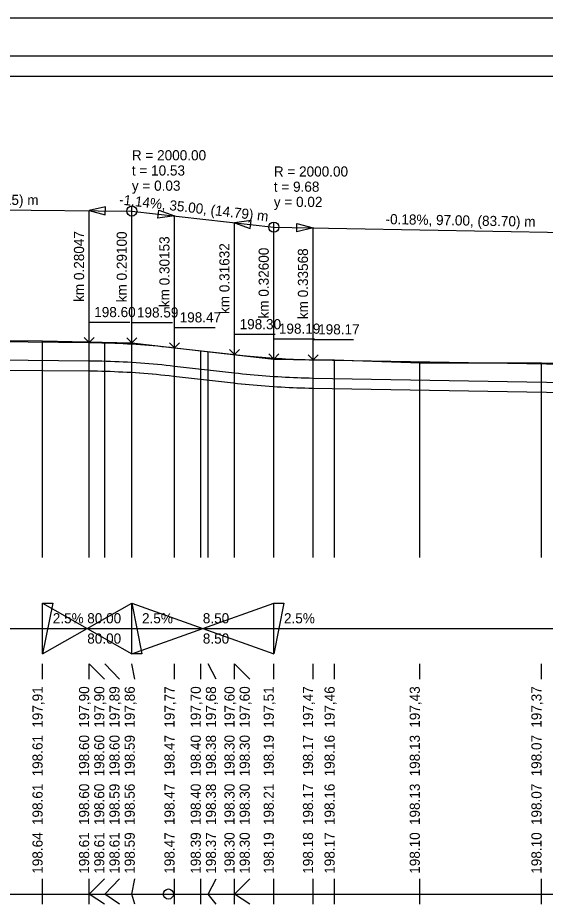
# Model space of a CAD drawing. Extents: x -51 to 53, y -74 to 15.
# Drawn here: x -12.15 to 0.85, y -6.73 to 15.15 of the extents above; entities that cross this region are included whole.
import ezdxf

# ---------------------------------------------------------------- set-up
doc = ezdxf.new("R2010")
doc.units = 0
for name, color, linetype in [('Implicitní', 7, 'Continuous'), ('KONSTRUKCE_L', 7, 'Continuous'), ('KOTY_L', 7, 'Continuous'), ('KOTY_N', 7, 'Continuous'), ('KOTY_S', 7, 'Continuous'), ('KOTY_T', 7, 'Continuous'), ('KOTY_VP', 7, 'Continuous'), ('Nová vrstva (0)', 7, 'Continuous'), ('PR_SKLON_L', 7, 'Continuous'), ('PR_SKLON_T', 7, 'Continuous'), ('ROVINA_L', 7, 'Continuous'), ('ROVINA_O', 7, 'Continuous'), ('SKLON_POMERY', 7, 'Continuous'), ('TABULKY_L', 7, 'Continuous'), ('TEREN_L', 7, 'Continuous'), ('V_POLYGON', 7, 'Continuous'), ('V_POLYGON_ZO', 7, 'Continuous')]:
    doc.layers.add(name, color=color, linetype=linetype)

msp = doc.modelspace()

# ---------------------------------------------------------------- linework, layer by layer
at = {"layer": 'Implicitní'}
msp.add_lwpolyline([(-51.392, 15.154), (53.079, 15.154), (53.079, -14.546), (-51.392, -14.546)], close=True, dxfattribs=at)
at = {"layer": 'KONSTRUKCE_L'}
for p, q in [((-16.608, 6.754), (-10.393, 6.698)), ((-10.393, 6.698), (-10.288, 6.697)), ((-10.288, 6.697), (-10.182, 6.695)), ((-10.182, 6.695), (-10.077, 6.693)), ((-10.077, 6.693), (-9.972, 6.69)), ((-9.972, 6.69), (-9.867, 6.687)), ((-9.867, 6.687), (-9.761, 6.683)), ((-9.761, 6.683), (-9.656, 6.678)), ((-9.656, 6.678), (-9.551, 6.673)), ((-9.551, 6.673), (-9.445, 6.667)), ((-9.445, 6.667), (-9.34, 6.661)), ((-9.34, 6.661), (-9.235, 6.654)), ((-9.235, 6.654), (-9.129, 6.647)), ((-9.129, 6.647), (-9.024, 6.639)), ((-9.024, 6.639), (-8.919, 6.631)), ((-8.919, 6.631), (-8.813, 6.622)), ((-8.813, 6.622), (-8.708, 6.612)), ((-8.708, 6.612), (-8.603, 6.602)), ((-8.603, 6.602), (-8.498, 6.591)), ((-8.498, 6.591), (-8.392, 6.58)), ((-8.392, 6.58), (-8.287, 6.568)), ((-8.287, 6.568), (-6.808, 6.399)), ((-6.808, 6.399), (-6.711, 6.389)), ((-6.711, 6.389), (-6.614, 6.378)), ((-6.614, 6.378), (-6.517, 6.368)), ((-6.517, 6.368), (-6.421, 6.359)), ((-6.421, 6.359), (-6.324, 6.35)), ((-6.324, 6.35), (-6.227, 6.341)), ((-6.227, 6.341), (-6.13, 6.333)), ((-6.13, 6.333), (-6.034, 6.326)), ((-6.034, 6.326), (-5.937, 6.319)), ((-5.937, 6.319), (-5.84, 6.312)), ((-5.84, 6.312), (-5.743, 6.306)), ((-5.743, 6.306), (-5.646, 6.3)), ((-5.646, 6.3), (-5.55, 6.295)), ((-5.55, 6.295), (-5.453, 6.29)), ((-5.453, 6.29), (-5.356, 6.286)), ((-5.356, 6.286), (-5.259, 6.282)), ((-5.259, 6.282), (-5.163, 6.279)), ((-5.163, 6.279), (-5.066, 6.276)), ((-5.066, 6.276), (-4.969, 6.274)), ((-4.969, 6.274), (-4.872, 6.272)), ((-4.872, 6.272), (3.497, 6.125))]:
    msp.add_line(p, q, dxfattribs=at)
at = {"layer": 'KOTY_L'}
for p, q in [((-11.54, 1.849), (-11.54, 7.189)), ((-10.393, 1.849), (-10.393, 7.163)), ((-10.393, 1.849), (-10.393, 7.163)), ((-10.01, 1.849), (-10.01, 7.154)), ((-9.34, 1.849), (-9.34, 7.139)), ((-8.287, 1.849), (-8.287, 7.015)), ((-7.64, 1.849), (-7.64, 6.939)), ((-7.462, 1.849), (-7.462, 6.919)), ((-6.808, 1.849), (-6.808, 6.846)), ((-6.808, 1.849), (-6.808, 6.846)), ((-5.84, 1.849), (-5.84, 6.739)), ((-4.872, 1.849), (-4.872, 6.726)), ((-4.34, 1.849), (-4.34, 6.719)), ((-2.24, 1.849), (-2.24, 6.649)), ((0.76, 1.849), (0.76, 6.649)), ((-11.54, -1.151), (-11.54, -0.776)), ((-10.393, -1.151), (-10.393, -0.776)), ((-10.018, -1.151), (-10.393, -0.776)), ((-9.643, -1.151), (-10.01, -0.776)), ((-9.268, -1.151), (-9.34, -0.776)), ((-8.287, -1.151), (-8.287, -0.776)), ((-7.64, -1.151), (-7.64, -0.776)), ((-7.265, -1.151), (-7.462, -0.776)), ((-6.808, -1.151), (-6.808, -0.776)), ((-6.433, -1.151), (-6.808, -0.776)), ((-5.84, -1.151), (-5.84, -0.776)), ((-4.872, -1.151), (-4.872, -0.776)), ((-4.34, -1.151), (-4.34, -0.776)), ((-2.24, -1.151), (-2.24, -0.776)), ((0.76, -1.151), (0.76, -0.776)), ((-11.54, -4.751), (-11.54, -4.751)), ((-10.393, -4.751), (-10.393, -4.751)), ((-10.018, -4.751), (-10.018, -4.751)), ((-9.643, -4.751), (-9.643, -4.751)), ((-9.268, -4.751), (-9.268, -4.751)), ((-8.287, -4.751), (-8.287, -4.751)), ((-7.64, -4.751), (-7.64, -4.751)), ((-7.265, -4.751), (-7.265, -4.751)), ((-6.808, -4.751), (-6.808, -4.751)), ((-6.433, -4.751), (-6.433, -4.751)), ((-5.84, -4.751), (-5.84, -4.751)), ((-4.872, -4.751), (-4.872, -4.751)), ((-4.34, -4.751), (-4.34, -4.751)), ((-2.24, -4.751), (-2.24, -4.751)), ((0.76, -4.751), (0.76, -4.751)), ((-11.54, -6.451), (-11.54, -6.076)), ((-10.393, -6.451), (-10.393, -6.076)), ((-10.393, -6.451), (-10.018, -6.076)), ((-10.01, -6.451), (-9.643, -6.076)), ((-9.34, -6.451), (-9.268, -6.076)), ((-8.287, -6.451), (-8.287, -6.076)), ((-7.64, -6.451), (-7.64, -6.076)), ((-7.462, -6.451), (-7.265, -6.076)), ((-6.808, -6.451), (-6.808, -6.076)), ((-6.808, -6.451), (-6.433, -6.076)), ((-5.84, -6.451), (-5.84, -6.076)), ((-4.872, -6.451), (-4.872, -6.076)), ((-4.34, -6.451), (-4.34, -6.076)), ((-2.24, -6.451), (-2.24, -6.076)), ((0.76, -6.451), (0.76, -6.076))]:
    msp.add_line(p, q, dxfattribs=at)
at = {"layer": 'KOTY_S'}
for p, q in [((-11.54, -6.701), (-11.54, -6.451)), ((-10.393, -6.701), (-10.393, -6.451)), ((-10.018, -6.701), (-10.393, -6.451)), ((-9.643, -6.701), (-10.01, -6.451)), ((-9.268, -6.701), (-9.34, -6.451)), ((-8.287, -6.701), (-8.287, -6.451)), ((-7.64, -6.701), (-7.64, -6.451)), ((-7.265, -6.701), (-7.462, -6.451)), ((-6.808, -6.701), (-6.808, -6.451)), ((-6.433, -6.701), (-6.808, -6.451)), ((-5.84, -6.701), (-5.84, -6.451)), ((-4.872, -6.701), (-4.872, -6.451)), ((-4.34, -6.701), (-4.34, -6.451)), ((-2.24, -6.701), (-2.24, -6.451)), ((0.76, -6.701), (0.76, -6.451))]:
    msp.add_line(p, q, dxfattribs=at)
at = {"layer": 'Nová vrstva (0)'}
for p, q in [((-16.61, 6.504), (-10.395, 6.448)), ((-10.396, 6.448), (-10.291, 6.447)), ((-10.292, 6.447), (-10.187, 6.445)), ((-10.188, 6.445), (-10.083, 6.443)), ((-10.084, 6.443), (-9.979, 6.44)), ((-9.98, 6.44), (-9.875, 6.437)), ((-9.876, 6.437), (-9.771, 6.433)), ((-9.772, 6.433), (-9.667, 6.428)), ((-9.668, 6.428), (-9.563, 6.423)), ((-9.564, 6.423), (-9.459, 6.418)), ((-9.46, 6.418), (-9.355, 6.412)), ((-9.356, 6.412), (-9.251, 6.405)), ((-9.252, 6.405), (-9.147, 6.398)), ((-9.148, 6.398), (-9.043, 6.39)), ((-9.044, 6.39), (-8.939, 6.381)), ((-8.94, 6.382), (-8.835, 6.373)), ((-8.836, 6.373), (-8.731, 6.363)), ((-8.732, 6.363), (-8.627, 6.353)), ((-8.628, 6.353), (-8.523, 6.343)), ((-8.524, 6.343), (-8.419, 6.332)), ((-8.42, 6.332), (-8.315, 6.32)), ((-8.315, 6.32), (-6.836, 6.151)), ((-6.835, 6.151), (-6.739, 6.14)), ((-6.737, 6.14), (-6.641, 6.13)), ((-6.639, 6.13), (-6.543, 6.12)), ((-6.542, 6.12), (-6.445, 6.11)), ((-6.444, 6.11), (-6.347, 6.101)), ((-6.346, 6.101), (-6.249, 6.092)), ((-6.248, 6.092), (-6.151, 6.084)), ((-6.15, 6.084), (-6.053, 6.077)), ((-6.052, 6.077), (-5.955, 6.069)), ((-5.954, 6.069), (-5.857, 6.063)), ((-5.856, 6.063), (-5.759, 6.057)), ((-5.758, 6.057), (-5.661, 6.051)), ((-5.66, 6.051), (-5.563, 6.046)), ((-5.562, 6.045), (-5.465, 6.041)), ((-5.464, 6.041), (-5.367, 6.036)), ((-5.366, 6.036), (-5.269, 6.033)), ((-5.268, 6.033), (-5.171, 6.029)), ((-5.17, 6.029), (-5.073, 6.026)), ((-5.072, 6.026), (-4.975, 6.024)), ((-4.974, 6.024), (-4.877, 6.022)), ((-4.877, 6.022), (3.493, 5.875))]:
    msp.add_line(p, q, dxfattribs=at)
at = {"layer": 'PR_SKLON_L'}
for p, q in [((-11.54, -0.526), (-9.34, 0.724)), ((-11.54, 0.724), (-9.34, -0.526)), ((-9.34, -0.526), (-5.84, 0.724)), ((-9.34, 0.724), (-5.84, -0.526)), ((-38.44, 0.099), (-11.54, 0.099)), ((-11.54, 0.099), (-9.34, 0.099)), ((-9.34, 0.099), (-5.84, 0.099)), ((-5.84, 0.099), (3.86, 0.099)), ((-9.34, -0.526), (-9.34, -0.526)), ((-5.84, -0.526), (-5.84, -0.526))]:
    msp.add_line(p, q, dxfattribs=at)
for points in [[(-11.54, 0.099), (-11.54, 0.724), (-11.29, 0.724), (-11.54, -0.526)], [(-9.34, 0.099), (-9.34, 0.724), (-9.09, -0.526), (-9.34, -0.526)], [(-5.84, 0.099), (-5.84, 0.724), (-5.59, 0.724), (-5.84, -0.526)]]:
    msp.add_lwpolyline(points, close=True, dxfattribs=at)
at = {"layer": 'ROVINA_L'}
msp.add_line((-38.44, -6.451), (50.86, -6.451), dxfattribs=at)
at = {"layer": 'ROVINA_O'}
msp.add_circle((-8.44, -6.451), 0.125, dxfattribs=at)
at = {"layer": 'SKLON_POMERY'}
for p, q in [((-9.34, 10.389), (-9.34, 10.514)), ((-17.14, 10.459), (-9.34, 10.389)), ((-10.393, 7.148), (-10.393, 10.398)), ((-9.34, 7.139), (-9.34, 10.389)), ((-9.34, 10.389), (-5.84, 9.989)), ((-8.287, 7.018), (-8.287, 10.268)), ((-6.808, 6.849), (-6.808, 10.099)), ((-5.84, 9.989), (-5.84, 10.114)), ((-5.84, 6.739), (-5.84, 9.989)), ((-5.84, 9.989), (3.86, 9.819)), ((-4.872, 6.722), (-4.872, 9.972))]:
    msp.add_line(p, q, dxfattribs=at)
for points in [[(-10.393, 10.398), (-9.994, 10.295), (-9.992, 10.495), (-10.393, 10.398)], [(-8.287, 10.268), (-8.696, 10.215), (-8.673, 10.413), (-8.287, 10.268)], [(-6.808, 10.099), (-6.422, 9.955), (-6.399, 10.153), (-6.808, 10.099)], [(-4.872, 9.972), (-5.274, 9.879), (-5.271, 10.079), (-4.872, 9.972)]]:
    msp.add_lwpolyline(points, close=True, dxfattribs=at)
for points in [[(-10.518, 7.273), (-10.393, 7.148), (-10.268, 7.273), (-10.393, 7.148), (-10.393, 7.648), (-9.393, 7.648)], [(-9.465, 7.264), (-9.34, 7.139), (-9.215, 7.264), (-9.34, 7.139), (-9.34, 7.639), (-8.34, 7.639)], [(-8.412, 7.143), (-8.287, 7.018), (-8.162, 7.143), (-8.287, 7.018), (-8.287, 7.518), (-7.287, 7.518)], [(-6.933, 6.974), (-6.808, 6.849), (-6.683, 6.974), (-6.808, 6.849), (-6.808, 7.349), (-5.808, 7.349)], [(-5.965, 6.864), (-5.84, 6.739), (-5.715, 6.864), (-5.84, 6.739), (-5.84, 7.239), (-4.84, 7.239)], [(-4.997, 6.847), (-4.872, 6.722), (-4.747, 6.847), (-4.872, 6.722), (-4.872, 7.222), (-3.872, 7.222)]]:
    msp.add_lwpolyline(points, dxfattribs=at)
for centre in [(-9.34, 10.389), (-5.84, 9.989)]:
    msp.add_circle(centre, 0.125, dxfattribs=at)
at = {"layer": 'TABULKY_L'}
for p, q in [((-38.44, 14.218), (50.86, 14.218)), ((-38.44, 13.718), (50.86, 13.718))]:
    msp.add_line(p, q, dxfattribs=at)
at = {"layer": 'TEREN_L'}
for p, q in [((-13.44, 7.209), (-11.54, 7.189)), ((-11.54, 7.189), (-9.34, 7.139)), ((-9.34, 7.139), (-7.64, 6.939)), ((-7.64, 6.939), (-5.84, 6.739)), ((-5.84, 6.739), (-4.34, 6.719)), ((-4.34, 6.719), (-2.24, 6.649)), ((-2.24, 6.649), (0.76, 6.649)), ((0.76, 6.649), (3.86, 6.569))]:
    msp.add_line(p, q, dxfattribs=at)
at = {"layer": 'V_POLYGON'}
for p, q in [((-16.608, 7.204), (-10.393, 7.148)), ((-8.287, 7.018), (-6.808, 6.849)), ((-4.872, 6.722), (3.497, 6.575))]:
    msp.add_line(p, q, dxfattribs=at)
for points in [[(-10.393, 7.148), (-10.288, 7.147), (-10.182, 7.145), (-10.077, 7.143), (-9.972, 7.14), (-9.867, 7.137), (-9.761, 7.133), (-9.656, 7.128), (-9.551, 7.123), (-9.445, 7.117), (-9.34, 7.111), (-9.235, 7.104), (-9.129, 7.097), (-9.024, 7.089), (-8.919, 7.081), (-8.813, 7.072), (-8.708, 7.062), (-8.603, 7.052), (-8.498, 7.041), (-8.392, 7.03), (-8.287, 7.018)], [(-6.808, 6.849), (-6.711, 6.839), (-6.614, 6.828), (-6.517, 6.818), (-6.421, 6.809), (-6.324, 6.8), (-6.227, 6.791), (-6.13, 6.783), (-6.034, 6.776), (-5.937, 6.769), (-5.84, 6.762), (-5.743, 6.756), (-5.646, 6.75), (-5.55, 6.745), (-5.453, 6.74), (-5.356, 6.736), (-5.259, 6.732), (-5.163, 6.729), (-5.066, 6.726), (-4.969, 6.724), (-4.872, 6.722)]]:
    msp.add_lwpolyline(points, dxfattribs=at)
at = {"layer": 'V_POLYGON_ZO'}
for p, q in [((-10.393, 7.148), (-9.34, 7.139)), ((-9.34, 7.139), (-8.287, 7.018)), ((-6.808, 6.849), (-5.84, 6.739)), ((-5.84, 6.739), (-4.872, 6.722))]:
    msp.add_line(p, q, dxfattribs=at)

# ---------------------------------------------------------------- texts
at = {"layer": 'KOTY_N'}
for s, p in [('198.61', (-11.54, -4.751)), ('198.60', (-10.393, -4.751)), ('198.60', (-10.018, -4.751)), ('198.59', (-9.643, -4.751)), ('198.56', (-9.268, -4.751)), ('198.47', (-8.287, -4.751)), ('198.40', (-7.64, -4.751)), ('198.38', (-7.265, -4.751)), ('198.30', (-6.808, -4.751)), ('198.30', (-6.433, -4.751)), ('198.21', (-5.84, -4.751)), ('198.17', (-4.872, -4.751)), ('198.16', (-4.34, -4.751)), ('198.13', (-2.24, -4.751)), ('198.07', (0.76, -4.751))]:
    msp.add_text(s, height=0.25, rotation=90, dxfattribs=at).set_placement(p)
at = {"layer": 'KOTY_T'}
for s, p in [('198.64', (-11.54, -5.951)), ('198.61', (-10.393, -5.951)), ('198.61', (-10.018, -5.951)), ('198.61', (-9.643, -5.951)), ('198.59', (-9.268, -5.951)), ('198.47', (-8.287, -5.951)), ('198.39', (-7.64, -5.951)), ('198.37', (-7.265, -5.951)), ('198.30', (-6.808, -5.951)), ('198.30', (-6.433, -5.951)), ('198.19', (-5.84, -5.951)), ('198.18', (-4.872, -5.951)), ('198.17', (-4.34, -5.951)), ('198.10', (-2.24, -5.951)), ('198.10', (0.76, -5.951))]:
    msp.add_text(s, height=0.25, rotation=90, dxfattribs=at).set_placement(p)
at = {"layer": 'KOTY_VP'}
for s, p in [('198.61', (-11.54, -3.551)), ('198.60', (-10.393, -3.551)), ('198.60', (-10.018, -3.551)), ('198.60', (-9.643, -3.551)), ('198.59', (-9.268, -3.551)), ('198.47', (-8.287, -3.551)), ('198.40', (-7.64, -3.551)), ('198.38', (-7.265, -3.551)), ('198.30', (-6.808, -3.551)), ('198.30', (-6.433, -3.551)), ('198.19', (-5.84, -3.551)), ('198.17', (-4.872, -3.551)), ('198.16', (-4.34, -3.551)), ('198.13', (-2.24, -3.551)), ('198.07', (0.76, -3.551))]:
    msp.add_text(s, height=0.25, rotation=90, dxfattribs=at).set_placement(p)
at = {"layer": 'Nová vrstva (0)'}
for s, p in [('197,91', (-11.54, -2.351)), ('197,90', (-10.393, -2.351)), ('197,90', (-10.018, -2.351)), ('197,89', (-9.643, -2.351)), ('197,86', (-9.268, -2.351)), ('197,77', (-8.287, -2.351)), ('197,70', (-7.64, -2.351)), ('197,68', (-7.265, -2.351)), ('197,60', (-6.808, -2.351)), ('197,60', (-6.433, -2.351)), ('197,51', (-5.84, -2.351)), ('197,47', (-4.872, -2.351)), ('197,46', (-4.34, -2.351)), ('197,43', (-2.24, -2.351)), ('197,37', (0.76, -2.351))]:
    msp.add_text(s, height=0.25, rotation=90, dxfattribs=at).set_placement(p)
at = {"layer": 'PR_SKLON_T'}
for s, p in [('2.5%', (-11.29, 0.224)), ('80.00', (-10.44, 0.224)), ('2.5%', (-9.09, 0.224)), ('8.50', (-7.59, 0.224)), ('2.5%', (-5.59, 0.224)), ('80.00', (-10.44, -0.276)), ('8.50', (-7.59, -0.276))]:
    msp.add_text(s, height=0.25, dxfattribs=at).set_placement(p)
at = {"layer": 'SKLON_POMERY'}
for s, p in [('R = 2000.00', (-9.34, 11.639)), ('t = 10.53', (-9.34, 11.264)), ('R = 2000.00', (-5.84, 11.239)), ('y = 0.03', (-9.34, 10.889)), ('t = 9.68', (-5.84, 10.864)), ('y = 0.02', (-5.84, 10.489)), ('198.60', (-10.268, 7.773)), ('198.59', (-9.215, 7.764)), ('198.47', (-8.162, 7.643)), ('198.30', (-6.683, 7.474)), ('198.19', (-5.715, 7.364)), ('198.17', (-4.747, 7.347))]:
    msp.add_text(s, height=0.25, dxfattribs=at).set_placement(p)
for s, rotation, p in [('-0.09%, 78.00, (62.15) m', 359.4858, (-15.339, 10.568)), ('-1.14%, 35.00, (14.79) m', 353.4802, (-9.662, 10.553)), ('-0.18%, 97.00, (83.70) m', 358.9959, (-3.087, 10.066)), ('km 0.28047', 90, (-10.518, 8.148)), ('km 0.29100', 90, (-9.465, 8.139)), ('km 0.30153', 90, (-8.412, 8.018)), ('km 0.31632', 90, (-6.933, 7.849)), ('km 0.32600', 90, (-5.965, 7.739)), ('km 0.33568', 90, (-4.997, 7.722))]:
    msp.add_text(s, height=0.25, rotation=rotation, dxfattribs=at).set_placement(p)

doc.saveas('drawing.dxf')
